// Mitsubishi GX Works2 project: MC-19MR-4MTS-F450-H3G-B   PLC: FX3G

PROGRAM MAIN
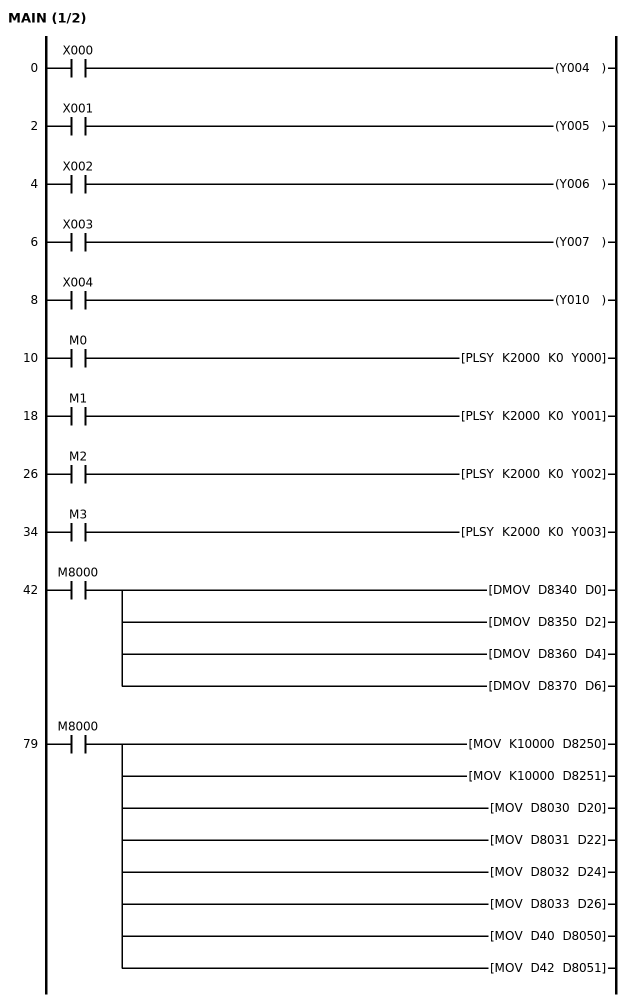
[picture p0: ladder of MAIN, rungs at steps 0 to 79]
0     LD      X000
      OUT     Y004
2     LD      X001
      OUT     Y005
4     LD      X002
      OUT     Y006
6     LD      X003
      OUT     Y007
8     LD      X004
      OUT     Y010
10    LD      M0
      PLSY    K2000 K0 Y000
18    LD      M1
      PLSY    K2000 K0 Y001
26    LD      M2
      PLSY    K2000 K0 Y002
34    LD      M3
      PLSY    K2000 K0 Y003
42    LD      M8000
      DMOV    D8340 D0
      DMOV    D8350 D2
      DMOV    D8360 D4
      DMOV    D8370 D6
79    LD      M8000
      MOV     K10000 D8250
      MOV     K10000 D8251
      MOV     D8030 D20
      MOV     D8031 D22
      MOV     D8032 D24
      MOV     D8033 D26
      MOV     D40 D8050
      MOV     D42 D8051
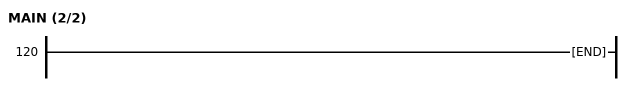
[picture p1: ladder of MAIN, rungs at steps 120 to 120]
120   END
END_PROGRAM
